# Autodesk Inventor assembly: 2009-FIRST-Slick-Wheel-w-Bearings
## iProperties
Created: 2009-03
Part Number: 2009-FIRST-Slick-Wheel-w-Bearings
Document SubType Name: Assembly
Designer: Pat
Author: Pat
Translation Standard: STEP AP214IS
FileName: \\OWNER-56CF2561A\Data\AndyMark\FIRST Kit\2009\09 C-Drive Base\09 FIRST Wheel with bearings.stp
PreProcessor: Autodesk Inventor 2008
PostProcessor: Build: 236a, Release: 2009 RTM - Date: Fri 02/22/2008
Sent Units: Inches
Uncertainty: 0.00039370078740199997
